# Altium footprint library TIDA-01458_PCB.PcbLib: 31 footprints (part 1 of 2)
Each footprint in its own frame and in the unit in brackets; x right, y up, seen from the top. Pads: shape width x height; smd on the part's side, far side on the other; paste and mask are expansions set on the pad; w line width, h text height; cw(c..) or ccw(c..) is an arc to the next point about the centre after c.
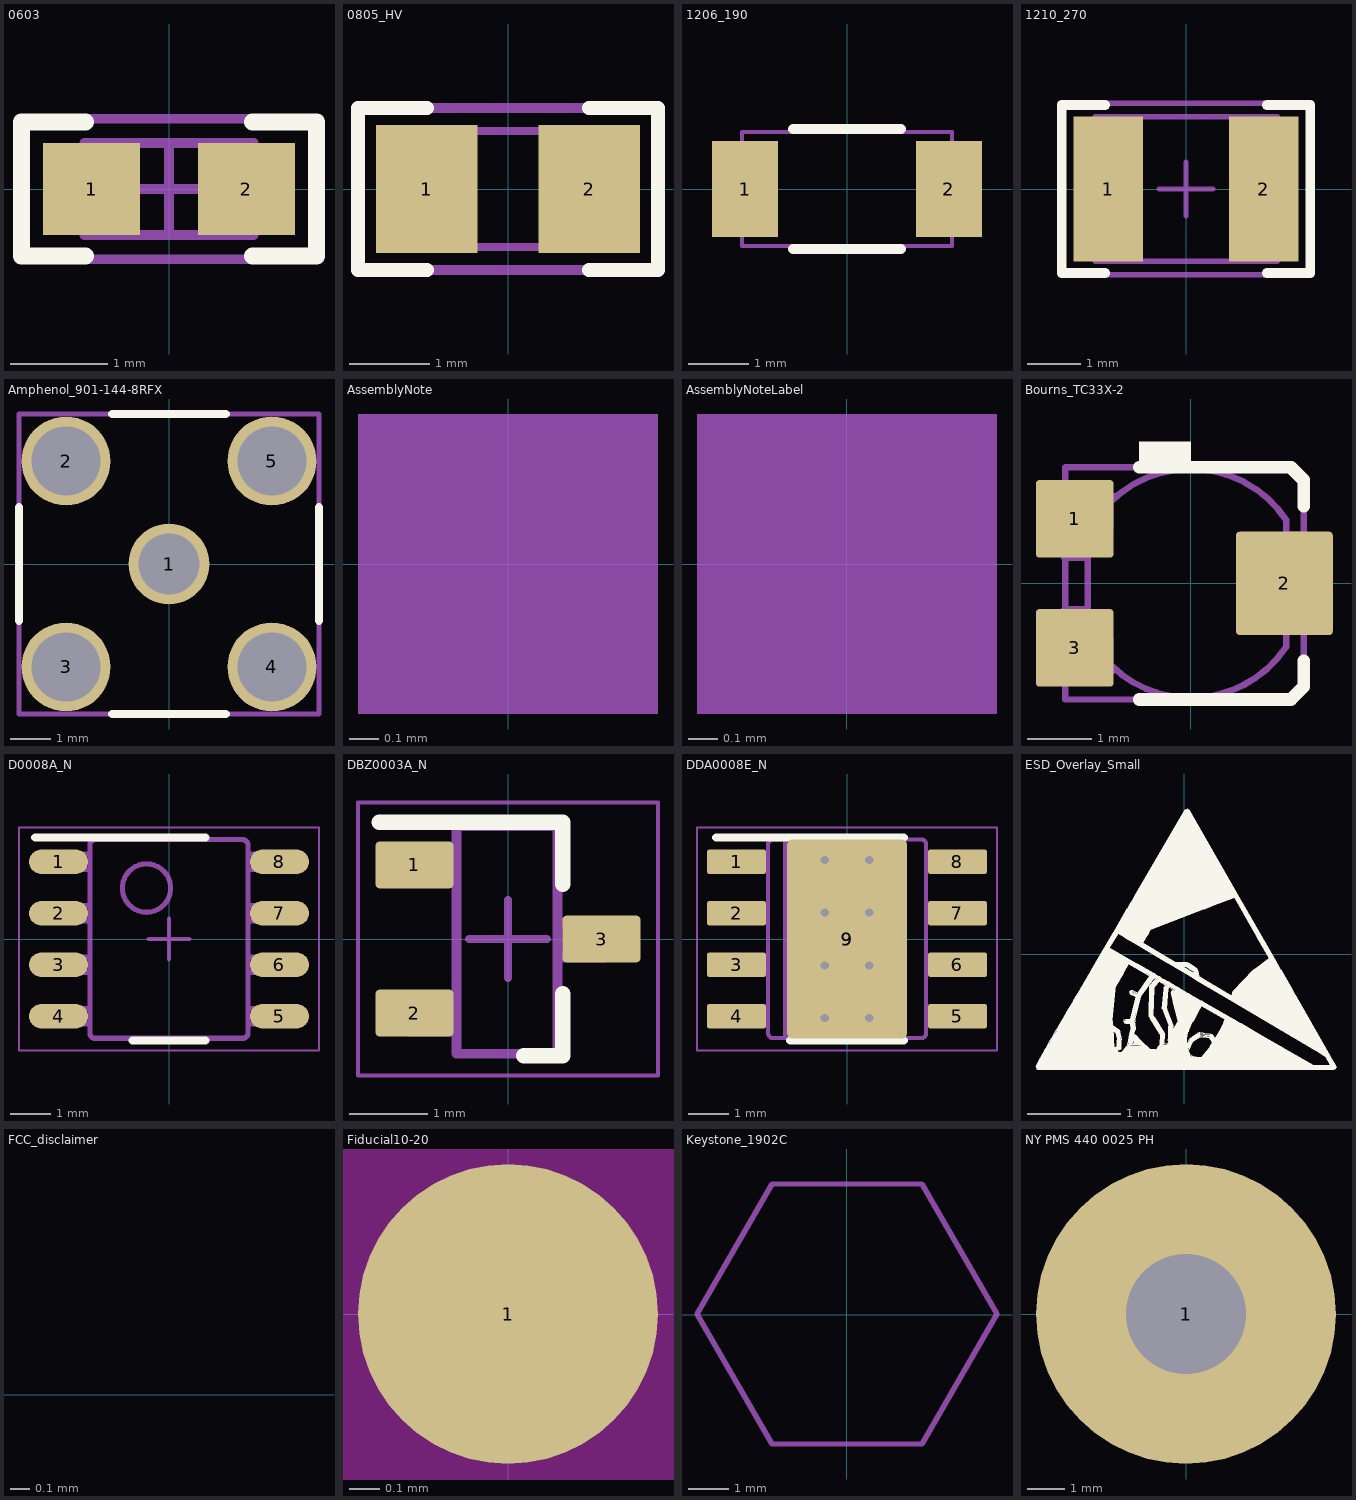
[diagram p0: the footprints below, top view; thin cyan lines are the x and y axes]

## 0603 [mm] "0603 from SM-752 data"
height 1
pads (2):
  rect 1x0.95 smd: 1(-0.8,0) 2(0.8,0)
Top Overlay:
  lines w0.178: -0.864,-0.691 -1.524,-0.691 -1.524,0.693 -0.864,0.693 ; 0.864,-0.691 1.524,-0.691 1.524,0.693 0.864,0.693
Mechanical 5:
  lines w0.1: -1.55,-0.725 1.55,-0.725 1.55,0.725 -1.55,0.725 -1.55,-0.725
  text ".Designator" at 1.219,0.356 h0.76
Mechanical 13:
  lines w0.1: -0.55,-0.475 -0.55,0.475 ; 0.55,-0.475 0.55,0.475 ; -0.875,-0.475 -0.875,0.475 0.875,0.475 0.875,-0.475 -0.875,-0.475
Mechanical 15:
  lines w0.1: -0.475,0 0.475,0 ; 0,-0.475 0,0.475 ; -1.55,-0.725 -1.55,0.725 1.55,0.725 1.55,-0.725 -1.55,-0.725
3D body: height 1, standoff 0, extent 0.551,-0.474 0.874,0.474
3D body: height 1, standoff 0, extent -0.549,-0.474 0.549,0.474
3D body: height 1, standoff 0, extent -0.874,-0.474 -0.551,0.474

## 0805_HV [mil] "0805 with 30mil clearance between pads"
height 57.09
pads (2):
  rect 50x63 smd: 1(-40,0) 2(40,0)
Top Overlay:
  lines w7: -40,-40 -74,-40 -74,0 -74,40 -40,40 ; 40,-40 74,-40 74,0 74,40 40,40
Mechanical 5:
  lines w5: -74,-40 74,-40 74,40 -74,40 -74,-40
  text ".Designator" at 47,15 h35
Mechanical 13:
  lines w3.94: -25.59,-28.54 -25.59,28.54 ; 25.59,-28.54 25.59,28.54 ; -43.31,-28.54 43.31,-28.54 43.31,28.54 -43.31,28.54 -43.31,-28.54
3D body: height 57.09, standoff 0, extent -43.29,-28.52 -25.61,28.52
3D body: height 57.09, standoff 0, extent -25.57,-28.52 25.57,28.52
3D body: height 57.09, standoff 0, extent 25.61,-28.52 43.29,28.52

## 1206_190 [mm] "1206_190"
height 1.9
pads (2):
  rect 1.1x1.6 smd: 1(-1.7,0) 2(1.7,0)
Top Overlay:
  lines w0.17: -0.9,-1 0.9,-1 ; -0.9,1 0.9,1
Mechanical 5:
  lines w0.07: -1.75,-0.95 1.75,-0.95 1.75,0.95 -1.75,0.95 -1.75,-0.95
  text ".Designator" at -1.5,-0.4 h0.81
3D body: height 1.9, standoff 0, extent -1.749,-0.949 -1.301,0.949
3D body: height 1.9, standoff 0, extent -1.299,-0.949 1.299,0.949
3D body: height 1.9, standoff 0, extent 1.301,-0.949 1.749,0.949

## 1210_270 [mm] "1210"
height 2.7
pads (2):
  rect 1.3x2.7 smd: 1(-1.45,0) 2(1.45,0)
Top Overlay:
  lines w0.178: -1.511,-1.568 -2.316,-1.568 -2.316,1.568 -1.511,1.568 ; 1.511,-1.568 2.316,-1.568 2.316,1.568 1.511,1.568
Mechanical 5:
  lines w0.1: -1.7,-1.35 1.7,-1.35 1.7,1.35 -1.7,1.35 -1.7,-1.35
  text ".Designator" at 0.635,0.457 h0.76
Mechanical 13:
  lines w0.1: -1.2,-1.35 -1.2,1.35 ; 1.2,-1.35 1.2,1.35 ; -1.7,-1.35 -1.7,1.35 1.7,1.35 1.7,-1.35 -1.7,-1.35
Mechanical 15:
  lines w0.1: -0.5,0 0.5,0 ; 0,-0.5 0,0.5 ; -2.35,-1.6 -2.35,1.6 2.35,1.6 2.35,-1.6 -2.35,-1.6
3D body: height 2.7, standoff 0, extent -1.699,-1.349 -1.201,1.349
3D body: height 2.7, standoff 0, extent -1.199,-1.349 1.199,1.349
3D body: height 2.7, standoff 0, extent 1.201,-1.349 1.699,1.349

## Amphenol_901-144-8RFX [mm] "SMA Straight Jack, TH"
height 9.93
pads (5):
  round 2 hole 1.5: 1(0,0)
  round 2.2 hole 1.7: 2(-2.54,2.54) 3(-2.54,-2.54) 4(2.54,-2.54) 5(2.54,2.54)
Top Overlay:
  lines w0.2: -3.7,-1.4 -3.7,1.4 ; -1.4,-3.7 1.4,-3.7 ; -1.4,3.7 1.4,3.7 ; 3.7,-1.4 3.7,1.4
Mechanical 5:
  lines w0.127: -3.7,-3.7 3.7,-3.7 3.7,3.7 -3.7,3.7 -3.7,-3.7
  text ".Designator" at -1.524,-0.508 h1.02
3D body: height 0.5, standoff -2.5, extent -0.63,-0.634 0.635,0.634
3D body: height 1, standoff 0, extent 2.03,2.03 3.7,3.7
3D body: height 1, standoff 0, extent 2.03,-3.7 3.7,-2.03
3D body: height 1, standoff 0, extent -3.7,-3.7 -2.03,-2.03
3D body: height 1, standoff 0, extent -3.7,2.03 -2.03,3.7
3D body: height 2, standoff 0.3, extent -3.7,-3.7 3.7,3.7
3D body: height 0, standoff -2.5, extent 2.03,2.03 3.05,3.05
3D body: height 0, standoff -2.5, extent 2.03,-3.05 3.05,-2.03
3D body: height 0, standoff -2.5, extent -3.05,-3.05 -2.03,-2.03
3D body: height 0, standoff -2.5, extent -3.05,2.03 -2.03,3.05
3D body: height 4, standoff 2, extent -2.48,-2.495 2.5,2.495
3D body: height 9.93, standoff 2, extent -2.039,0 2.039,2.039
3D body: height 9.93, standoff 2, extent -2.039,-2.039 2.039,-0.001
3D body: height 6.2, standoff 6, extent -2.411,0 2.411,2.411
3D body: height 6.2, standoff 6, extent -2.411,-2.411 2.411,-0.001
3D body: height 6.7, standoff 6.5, extent -2.411,0 2.411,2.411
3D body: height 6.7, standoff 6.5, extent -2.411,-2.411 2.411,-0.001
3D body: height 7.2, standoff 7, extent -2.411,0 2.411,2.411
3D body: height 7.2, standoff 7, extent -2.411,-2.411 2.411,-0.001
3D body: height 7.7, standoff 7.5, extent -2.411,0 2.411,2.411
3D body: height 7.7, standoff 7.5, extent -2.411,-2.411 2.411,-0.001
3D body: height 8.2, standoff 8, extent -2.411,0 2.411,2.411
3D body: height 8.2, standoff 8, extent -2.411,-2.411 2.411,-0.001
3D body: height 8.7, standoff 8.5, extent -2.411,0 2.411,2.411
3D body: height 8.7, standoff 8.5, extent -2.411,-2.411 2.411,-0.001
3D body: height 5.7, standoff 5.5, extent -2.411,0 2.411,2.411
3D body: height 5.7, standoff 5.5, extent -2.411,-2.411 2.411,-0.001

## AssemblyNote [mm] "Assembly Note"
Mechanical 5:
  rectangle: -0.508,-0.508 0.508,0.508
  text ".Comment" at 1.143,-0.508 h1.02
  text ".Designator" at -4.191,-0.508 h1.02

## AssemblyNoteLabel [mm] "Assembly Note for PCB Labels"
Mechanical 5:
  rectangle: -0.508,-0.508 0.508,0.508
  text "Install label in silkscreened box after final wash.  Text shall be 8 pt font.  Text shall be per the Label Table in the PDF schematic." at 1.143,-0.508 h1.02
  text ".Designator" at -4.191,-0.508 h1.02

## Bourns_TC33X-2 [mm] "SMD, 3-Leads, Body 3.8x3.6mm"
height 1.5
pads (3):
  rrect8% 1.2x1.2 smd: 1(-1.8,1) 3(-1.8,-1)
  rrect7% 1.5x1.6 smd: 2(1.45,0)
Top Overlay:
  region: -0.8,2.2 -0.8,1.8 0,1.8 0,2.2
  lines w0.2: -0.8,-1.8 1.55,-1.8 1.75,-1.6 1.75,-1.2 ; -0.8,1.8 1.55,1.8 1.75,1.6 1.75,1.2
Mechanical 5:
  lines w0.1: -1.95,-1.35 -1.95,-1.8 -1.9,-1.8 1.55,-1.8 1.75,-1.6 1.75,-0.75 1.476,-0.75 ; -1.95,-0.4 -1.95,0.4 ; -1.95,1.35 -1.95,1.8 -1.9,1.8 1.55,1.8 1.75,1.6 1.75,0.75 1.476,0.75 ; -1.6,-0.4 -1.925,-0.4 -1.963,-0.4 -1.963,-1.35 -1.925,-1.35 -1.152,-1.35 ; -1.6,0.4 -1.925,0.4 -1.963,0.4 -1.963,1.35 -1.925,1.35 -1.152,1.35 ; 1.476,-0.73 1.9,-0.73 1.9,-0.425 1.7,-0.425 1.7,-0.42 ; 1.476,0.73 1.9,0.73 1.9,0.425 1.7,0.425 1.7,0.42 ; 1.7,-0.42 1.7,0.42 ; 1.7,-0.42 1.8,-0.42 1.8,0.42 1.7,0.42 ; -1.6,-0.86 -1.6,0.86 -1.25,0.86 -1.25,1.26 cw(c0,0) 1.476,0.986 1.476,0.356 cw(c1.125,0) 1.476,-0.356 1.476,-0.986 cw(c0,0) -1.25,-1.26 -1.25,-0.86 -1.6,-0.86
  text ".Designator" at -1.194,-0.406 h1.5
3D body: height 1.13, standoff -0.02, extent -1.962,-1.8 2,1.8

## D0008A_N [mm] "SOIC, 8-Leads, Body 4.9x3.9mm, Pitch 1.27mm, IPC Medium Density"
height 1.75
pads (8):
  oval 1.45x0.6 smd: 1(-2.725,1.905) 2(-2.725,0.635) 3(-2.725,-0.635) 4(-2.725,-1.905) 5(2.725,-1.905) 6(2.725,-0.635) 7(2.725,0.635) 8(2.725,1.905)
Top Overlay:
  lines w0.2: -3.3,2.5 0.9,2.5 ; -0.9,-2.5 0.9,-2.5
Mechanical 5:
  lines w0.127: -2.375,-2.095 -2.375,-1.715 ; -2.375,-2.095 -2.589,-2.095 -3.002,-2.095 -3.002,-1.715 -2.589,-1.715 -2.375,-1.715 ; -2.375,-2.095 -1.995,-2.095 -1.952,-2.095 -1.952,-1.715 -1.995,-1.715 -2.375,-1.715 ; -2.375,-0.825 -2.375,-0.445 ; -2.375,-0.825 -2.589,-0.825 -3.002,-0.825 -3.002,-0.445 -2.589,-0.445 -2.375,-0.445 ; -2.375,-0.825 -1.995,-0.825 -1.952,-0.825 -1.952,-0.445 -1.995,-0.445 -2.375,-0.445 ; -2.375,0.445 -2.375,0.825 ; -2.375,0.445 -2.589,0.445 -3.002,0.445 -3.002,0.825 -2.589,0.825 -2.375,0.825 ; -2.375,0.445 -1.995,0.445 -1.952,0.445 -1.952,0.825 -1.995,0.825 -2.375,0.825 ; -2.375,1.715 -2.375,2.095 ; -2.375,1.715 -2.589,1.715 -3.002,1.715 -3.002,2.095 -2.589,2.095 -2.375,2.095 ; -2.375,1.715 -1.995,1.715 -1.952,1.715 -1.952,2.095 -1.995,2.095 -2.375,2.095 ; -0.332,-2.45 -0.182,-2.45 ; -0.332,-2.45 -0.182,-2.45 ; -0.332,-2.45 -1.825,-2.45 -1.826,-2.45 cw(c-1.825,-2.323) -1.952,-2.324 -1.952,-2.323 -1.952,2.323 -1.952,2.324 cw(c-1.825,2.323) -1.826,2.45 -1.825,2.45 -0.332,2.45 ; -0.332,2.45 -0.182,2.45 ; -0.332,2.45 -0.182,2.45 ; -0.182,-2.45 0.178,-2.45 ; -0.182,2.45 0.178,2.45 ; 0.178,-2.45 0.328,-2.45 ; 0.178,-2.45 0.328,-2.45 ; 0.178,2.45 0.328,2.45 ; 0.178,2.45 0.328,2.45 ; 0.328,-2.45 1.821,-2.45 1.822,-2.45 ccw(c1.821,-2.323) 1.948,-2.324 1.948,-2.323 1.948,2.323 1.948,2.324 ccw(c1.821,2.323) 1.822,2.45 1.821,2.45 0.328,2.45 ; 2.371,-2.095 2.371,-1.715 ; 2.371,-2.095 1.991,-2.095 1.948,-2.095 1.948,-1.715 1.991,-1.715 2.371,-1.715 ; 2.371,-2.095 2.585,-2.095 2.998,-2.095 2.998,-1.715 2.585,-1.715 2.371,-1.715 ; 2.371,-0.825 2.371,-0.445 ; 2.371,-0.825 1.991,-0.825 1.948,-0.825 1.948,-0.445 1.991,-0.445 2.371,-0.445 ; 2.371,-0.825 2.585,-0.825 2.998,-0.825 2.998,-0.445 2.585,-0.445 2.371,-0.445 ; 2.371,0.445 2.371,0.825 ; 2.371,0.445 1.991,0.445 1.948,0.445 1.948,0.825 1.991,0.825 2.371,0.825 ; 2.371,0.445 2.585,0.445 2.998,0.445 2.998,0.825 2.585,0.825 2.371,0.825 ; 2.371,1.715 2.371,2.095 ; 2.371,1.715 1.991,1.715 1.948,1.715 1.948,2.095 1.991,2.095 2.371,2.095 ; 2.371,1.715 2.585,1.715 2.998,1.715 2.998,2.095 2.585,2.095 2.371,2.095 ; -0.555,0.659 ccw(c-0.555,1.256) -0.555,1.853 ccw(c-0.555,1.256) -0.555,0.659
  text ".Designator" at -1.625,-0.625 h0.89
Mechanical 15:
  lines w0.05: -3.7,-2.75 -3.7,2.75 3.7,2.75 3.7,-2.75 -3.7,-2.75
  lines w0.1: -0.5,0 0.5,0 ; 0,-0.5 0,0.5
3D body: height 1.63, standoff 0, extent -3,-2.45 3,2.45

## DBZ0003A_N [mm] "SOT23, 3-Leads, Body 2.9x1.3mm, Pitch 0.95mm, Lead Span 2.4mm, IPC Medium Density"
height 1.12
pads (3):
  rrect17% 1x0.6 smd: 1(-1.2,0.95) 2(-1.2,-0.95) 3(1.2,0)
Top Overlay:
  lines w0.2: -1.651,1.5 0.7,1.5 0.7,0.7 ; 0.2,-1.5 0.7,-1.5 0.7,-0.7
Mechanical 5:
  lines w0.127: -1.27,-1.187 -1.27,-0.743 -1.063,-0.743 -1.005,-0.743 -0.814,-0.743 -0.66,-0.743 -0.66,-1.187 -0.814,-1.187 -1.005,-1.187 -1.063,-1.187 -1.27,-1.187 ; -1.27,0.718 -1.27,1.162 -1.063,1.162 -1.005,1.162 -0.814,1.162 -0.66,1.162 -0.66,0.718 -0.814,0.718 -1.005,0.718 -1.063,0.718 -1.27,0.718 ; -0.66,-1.473 -0.66,1.448 0.635,1.448 0.635,-1.473 -0.66,-1.473 ; 0.635,-0.235 0.789,-0.235 0.98,-0.235 1.037,-0.235 1.245,-0.235 1.245,0.21 1.037,0.21 0.98,0.21 0.789,0.21 0.635,0.21 0.635,-0.235
  text ".Designator" at 0.33,-0.559 h0.51
Mechanical 15:
  lines w0.05: -1.925,-1.75 1.925,-1.75 1.925,1.75 -1.925,1.75 -1.925,-1.75
  lines w0.1: -0.5,0 0.5,0 ; 0,-0.5 0,0.5
3D body: height 0.98, standoff 0, extent -1.257,-1.461 1.258,1.461

## DDA0008E_N [mm]
height 1.7
pads (11):
  rrect17% 1.45x0.6 smd: 1(-2.725,1.905) 2(-2.725,0.635) 3(-2.725,-0.635) 4(-2.725,-1.905) 5(2.725,-1.905) 6(2.725,-0.635) 7(2.725,0.635) 8(2.725,1.905)
  rrect7% 2.95x4.9 smd paste-1.5: 9(0,0)
  rrect50% 2.4x3.1 on Top Paste: 9(0,0)
  rrect50% 2.4x3.1 on Top Solder: 9(0,0)
via 0.55,1.95 diameter 0.5 hole 0.2
via -0.55,1.95 diameter 0.5 hole 0.2
via -0.55,0.65 diameter 0.5 hole 0.2
via 0.55,-0.65 diameter 0.5 hole 0.2
via -0.55,-0.65 diameter 0.5 hole 0.2
via -0.55,-1.95 diameter 0.5 hole 0.2
via 0.55,-1.95 diameter 0.5 hole 0.2
via 0.55,0.65 diameter 0.5 hole 0.2
Top Overlay:
  lines w0.2: -3.225,2.5 1.4,2.5 ; -1.4,-2.5 1.4,-2.5
Mechanical 5:
  lines w0.1: -1.946,-2.321 ccw(c-1.819,-2.32) -1.82,-2.447 ; -1.946,-2.321 -1.946,-2.32 -1.946,2.329 ; -1.946,2.33 -1.946,2.329 ; -1.524,-2.447 -1.524,2.456 ; -1.946,2.33 cw(c-1.819,2.329) -1.82,2.456 ; -1.819,-2.447 1.826,-2.447 1.827,-2.447 ccw(c1.826,-2.32) 1.953,-2.321 1.953,-2.32 1.953,2.329 ; -1.82,-2.447 -1.819,-2.447 ; -1.82,2.456 -1.819,2.456 ; -1.819,2.456 1.826,2.456 1.827,2.456 cw(c1.826,2.329) 1.953,2.33 ; 1.953,2.329 1.953,2.33 ; -2.975,-2.091 -2.975,-1.71 -2.614,-1.71 -2.497,-1.71 -2.473,-1.71 -2.144,-1.71 -1.946,-1.71 -1.946,-2.091 -2.144,-2.091 -2.473,-2.091 -2.497,-2.091 -2.614,-2.091 -2.975,-2.091 ; -2.975,-0.821 -2.975,-0.44 -2.614,-0.44 -2.497,-0.44 -2.473,-0.44 -2.144,-0.44 -1.946,-0.44 -1.946,-0.821 -2.144,-0.821 -2.473,-0.821 -2.497,-0.821 -2.614,-0.821 -2.975,-0.821 ; -2.975,0.449 -2.975,0.83 -2.614,0.83 -2.497,0.83 -2.473,0.83 -2.144,0.83 -1.946,0.83 -1.946,0.449 -2.144,0.449 -2.473,0.449 -2.497,0.449 -2.614,0.449 -2.975,0.449 ; -2.975,1.719 -2.975,2.1 -2.614,2.1 -2.497,2.1 -2.473,2.1 -2.144,2.1 -1.946,2.1 -1.946,1.719 -2.144,1.719 -2.473,1.719 -2.497,1.719 -2.614,1.719 -2.975,1.719 ; -0.632,1.16 ccw(c-0.632,1.478) -0.632,1.795 ccw(c-0.632,1.478) -0.632,1.16 ; 1.953,-2.091 1.953,-1.71 2.15,-1.71 2.479,-1.71 2.503,-1.71 2.621,-1.71 2.981,-1.71 2.981,-2.091 2.621,-2.091 2.503,-2.091 2.479,-2.091 2.15,-2.091 1.953,-2.091 ; 1.953,-0.821 1.953,-0.44 2.15,-0.44 2.479,-0.44 2.503,-0.44 2.621,-0.44 2.981,-0.44 2.981,-0.821 2.621,-0.821 2.503,-0.821 2.479,-0.821 2.15,-0.821 1.953,-0.821 ; 1.953,0.449 1.953,0.83 2.15,0.83 2.479,0.83 2.503,0.83 2.621,0.83 2.981,0.83 2.981,0.449 2.621,0.449 2.503,0.449 2.479,0.449 2.15,0.449 1.953,0.449 ; 1.953,1.719 1.953,2.1 2.15,2.1 2.479,2.1 2.503,2.1 2.621,2.1 2.981,2.1 2.981,1.719 2.621,1.719 2.503,1.719 2.479,1.719 2.15,1.719 1.953,1.719
  text ".Designator" at -0.635,-0.889 h1.85
Mechanical 15:
  lines w0.05: -3.7,-2.75 3.7,-2.75 3.7,2.75 -3.7,2.75 -3.7,-2.75
  lines w0.1: -0.5,0 0.5,0 ; 0,-0.5 0,0.5
3D body: height 1.57, standoff 0, extent -3,-2.45 3,2.45

## ESD_Overlay_Small [mm]
Top Overlay:
  drawing of 901 lines, arcs and shapes, not listed

## FCC_disclaimer [mm]
height 1
Top Overlay:
  text "For evaluation only; not FCC approved for resale." at -15.928,-0.353 h1.52

## Fiducial10-20 [mm]
pads (1):
  round 1 smd mask+0.5: 1(0,0)
Top Layer keep-out:
  circle w1.178: c0,0 r0.5

## Keystone_1902C [mm] "Hex Standoff, 4-40 threaded, nylon"
height 12.7
Mechanical 5:
  lines w0.127: -3.69,0.012 -1.843,3.212 1.852,3.212 3.7,0.012 1.852,-3.188 -1.843,-3.188 -3.69,0.012
  text ".Designator" at -1.524,-0.508 h1.02
3D body: height 12.73, standoff 0.03, extent -3.682,-3.2 3.708,3.2

## NY PMS 440 0025 PH [mm] "4-40 nylon screw and mounting hole"
height 1.905
pads (1):
  round 8 hole 3.2: 1(0,0)
Mechanical 5:
  circle w0.127: c0,0 r3.789
  text ".Designator" at -0.671,-0.432 h1.02
3D body: height 2.69, standoff -8.74, extent -3.302,-3.3 3.296,3.3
